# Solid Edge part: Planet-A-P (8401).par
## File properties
Title: Planet A/P
Author: DESYS
Template: Normal.par
Last saved by: s.pallini
Revision: 12
Application: Solid Edge
Tipo di contenuto documento: 0
Precisione: 0,990
Document Number: 8401
Revision: 0
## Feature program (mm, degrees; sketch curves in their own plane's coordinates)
lofted protrusion "unnamed LoftedProtrusion 1"
sketch for "unnamed Protrusion 1" plane through (0, 0, 447) normal (0, 0, 1) x-axis (1, 0, 0)
  line (-263.8082, -135) -> (-147.5635, -135)
  line (-263.8082, 135) -> (-263.8082, -135)
  line (-263.8082, 135) -> (-147.5635, 135)
  dimension (linear) = 263.8082
extrude "unnamed Protrusion 1" add to key point along -normal
sketch for "unnamed Cutout 1" plane through (0, 0, 0) normal (0, -1, 0) x-axis (1, 0, 0)
  line (-263.8082, 447) -> (211.175, 360)
extrude "unnamed Cutout 1" cut through
sketch for "ExtrudedCutout_2" plane through (0, 0, 430) normal (0, 0, 1) x-axis (1, 0, 0)
  circle centre (7.2353, 0) radius 173.2534
extrude "ExtrudedCutout_2" cut finite 110 along -normal
lofted cutout "unnamed LoftedCutout 1"
sketch for "ExtrudedCutout_3" plane through (0, 0, 0) normal (0, -1, 0) x-axis (1, 0, 0)
  line (-191.006, 180) -> (-191.006, -23.5209)
  line (-263.8082, 180) -> (-191.006, 180)
  line (-263.8082, 397) -> (-263.8082, 180)
  line (-263.8082, 397) -> (-173.278, 397)
  arc centre (-38.4455, 309.6496) radius 160.6546 from (-173.278, 397) to (-95.4684, 159.4555) ccw
  line (-95.4684, 159.4555) -> (-95.4684, 0)
extrude "ExtrudedCutout_3" cut finite 210 symmetric
sketch for "unnamed Cutout 2" plane through (0, 0, 0) normal (0, 0, 1) x-axis (1, 0, 0)
  line (-95.4684, -105) -> (8.5066, -95.764)
  arc centre (-2.9504, 0) radius 96.4469 from (8.5066, 95.764) to (8.5066, -95.764) cw
  line (-95.4684, 105) -> (8.5066, 95.764)
  line (-95.4684, 105) -> (-95.4684, -105)
extrude "unnamed Cutout 2" cut to key point along +normal
sketch for "ExtrudedProtrusion_2" plane through (0, 0, 190) normal (0, 0, 1) x-axis (1, 0, 0)
  line (-90, -70) -> (60, -70)
  line (60, -70) -> (60, 70)
  line (60, 70) -> (-90, 70)
  line (-90, 70) -> (-90, -70)
  dimension (linear) = 90
  dimension (linear) = 60
extrude "ExtrudedProtrusion_2" add finite 180 along -normal  Treatment1_DraftAngle = 5 deg
fillet "Rotondo_1" radius 40
fillet "Rotondo_2" radius 30
sketch for "unnamed Cutout 3" plane through (-263.8082, 0, 205) normal (-1, 0, 0) x-axis (0, -1, 0)
  line (-90, -25) -> (90, -25)
extrude "unnamed Cutout 3" cut through along -normal
sketch for "unnamed Protrusion 2" plane through (-263.8082, 0, 205) normal (-1, 0, 0) x-axis (0, -1, 0)
  circle centre (0, -20) radius 50
extrude "unnamed Protrusion 2" add through along -normal
sketch for "ExtrudedCutout_6" plane through (0, 0, 0) normal (0, -1, 0) x-axis (1, 0, 0)
  line (50, 190) -> (33.6666, 61.5312)
  arc centre (3.9062, 65.3149) radius 30 from (3.9062, 35.3149) to (33.6666, 61.5312) ccw
  line (-34.4205, 35.3149) -> (3.9062, 35.3149)
  arc centre (-34.4205, 65.3149) radius 30 from (-63.3356, 57.3198) to (-34.4205, 35.3149) ccw
  line (-63.3356, 57.3198) -> (-84.6468, 160.6314)
  line (-84.6468, 160.6314) -> (-147.9995, 220.4026)
  line (-147.9995, 220.4026) -> (-125.2315, 220.4026)
  line (-125.2315, 220.4026) -> (-67.5978, 188.5269)
  line (-46.1658, 66.9955) -> (-67.5978, 188.5269)
  arc centre (-38.2874, 68.3848) radius 8 from (-46.1658, 66.9955) to (-38.2874, 60.3848) ccw
  line (-33.9784, 60.3848) -> (-38.2874, 60.3848)
  arc centre (-33.9784, 64.3848) radius 4 from (-33.9784, 60.3848) to (-30.0285, 65.016) ccw
  line (-50, 190) -> (-30.0285, 65.016)
extrude "ExtrudedCutout_6" cut finite 100 symmetric
sketch for "unnamed Cutout 4" plane through (-263.8082, 0, 180) normal (-1, 0, 0) x-axis (0, -1, 0)
  circle centre (0, 5) radius 40
extrude "unnamed Cutout 4" cut to key point along -normal
sketch for "unnamed Cutout 5" plane through (-125.2315, 0, 169.4609) normal (-1, 0, 0) x-axis (0, -1, 0)
  arc centre (0, 15.5391) radius 40 from (37.4991, 29.4609) to (-37.4991, 29.4609) cw
  line (-37.4991, 29.4609) -> (37.4991, 29.4609)
extrude "unnamed Cutout 5" cut through along -normal
fillet "Rotondo_3" radius 10
fillet "Rotondo_4" radius 10
fillet "Rotondo_5" radius 30
fillet "Rotondo_6" radius 5
fillet "Rotondo_7" radius 15
fillet "Rotondo_8" radius 40
fillet "Rotondo_9" radius 10
fillet "Rotondo_10" radius 20
fillet "Rotondo_12" radius 5
sketch for "unnamed Protrusion 3" plane through (-263.8082, 0, 204.4547) normal (-1, 0, 0) x-axis (0, -1, 0)
  circle centre (0, 172.5453) radius 45
extrude "unnamed Protrusion 3" add through along -normal
sketch for "ExtrudedCutout_9" plane through (-263.8082, 0, 204.4547) normal (-1, 0, 0) x-axis (0, -1, 0)
  circle centre (0, 172.5453) radius 27.5
extrude "ExtrudedCutout_9" cut finite 80 along -normal
fillet "unnamed Round 1"
sketch for "Foro_1" plane through (-20.561, 0.5154, 402.4458) normal (0.180167, 0, 0.983636) x-axis (0, -1, 0)
  hole centre (90.5154, -175.296) bore radius 10
hole "Foro_1" diameter 20 through
sketch for "unnamed Hole 1" plane through (-20.561, 0.5154, 402.4458) normal (0.180167, 0, 0.983636) x-axis (0, -1, 0)
  hole centre (-89.4846, -175.296) bore radius 10
hole "unnamed Hole 1" through
pattern "unnamed Pattern 1" of "Foro_1", "unnamed Hole 1"
sketch for "RevolvedCutout_1" plane through (0, 0, 0) normal (0, -1, 0) x-axis (1, 0, 0)
revolve "RevolvedCutout_1" cut finite 260 deg
sketch for "ExtrudedProtrusion_5" #1 plane through (-120, 0, 0) normal (1, 0, 0) x-axis (0, 1, 0)
sketch for "ExtrudedProtrusion_5" #2 plane through (-120, 0, 0) normal (1, 0, 0) x-axis (0, 1, 0)
extrude "ExtrudedProtrusion_5" add to key point along +normal  Profile_Plane1_Distance = 120 mm
fillet "Rotondo_14" radius 5
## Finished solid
Body 1: solid body, 186 faces, 452 edges, 266 vertices.
  Faces by surface: cylinder 68, plane 48, blend 36, torus 25, sphere 8, spline 1
  Edges by curve: circle 170, line 158, intersection 91, ellipse 33
Bounding box of the edges (mm; curved faces can reach further): 485.297 x 429.897 x 445.380, from (-263.8082, -214.9482, -0.3778) to (221.4884, 214.9494, 445.002).
Cylindrical faces by radius (mm): R4 x1, R5 x28, R8 x1, R10 x14, R20 x2, R27.5 x1, R30 x8, R40 x7, R45 x1, R50 x1, R90 x1, R96.4469 x1, R160.6546 x1, R173.2534 x1
Toroidal faces (ring radius, tube radius in mm): R-323.8082 r550 x1, R5 r5 x4, R9 r5 x2, R10 r5 x6, R13 r5 x2, R40 r5 x1, R45 r5 x1, R60 r20 x2, R76.4469 r20 x1, R78.3106 r114.4885 x1, R95 r5 x2, R180.6546 r20 x2
Spherical faces by radius (mm): R5 x4, R10 x4
Planar faces by outward normal: +x 3, +y 4, +z 3, -x 4, -y 4, -z 12, oblique 18
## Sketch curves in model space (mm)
arc centre (0, 9.2575, 385.8062) radius 200 from (0, 50, 190) through (0, 141.1846, 235.489) to (0, 198.1213, 320)
arc centre (0, -9.2575, 385.8062) radius 200 from (0, -198.1213, 320) through (0, -141.1846, 235.489) to (0, -50, 190)
arc centre (-1.549, 0, 384.0425) radius 200 from (-191.0181, 0, 320) through (-137.1089, 0, 236.9932) to (-50, 0, 190)
arc centre (-4.692, 0, 413.4027) radius 230 from (205.4887, 0, 320) through (142.8356, 0, 236.9499) to (50, 0, 190)
arc centre (20, -20, 190) radius 30 from (20, -50, 190) through (41.8212, -40.5872, 190) to (50, -20, 190)
line (50, -20, 190) -> (50, 20, 190)
arc centre (20, 20, 190) radius 30 from (20, 50, 190) through (41.8212, 40.5872, 190) to (50, 20, 190)
line (20, 50, 190) -> (-45, 50, 190)
arc centre (-45, 45, 190) radius 5 from (-50, 45, 190) through (-48.4312, 48.6369, 190) to (-45, 50, 190)
line (-50, 45, 190) -> (-50, -45, 190)
arc centre (-45, -45, 190) radius 5 from (-50, -45, 190) through (-48.4312, -48.6369, 190) to (-45, -50, 190)
line (-45, -50, 190) -> (20, -50, 190)
circle centre (7.2353, 0, 320) radius 198.2534
arc centre (-323.8082, 0, 279.2951) radius 550 from (200, 0, 447) through (222.7829, 0, 218.1552) to (150, 0, 0)
circle centre (0, 0, 447) radius 200
circle centre (0, 0, 0) radius 150
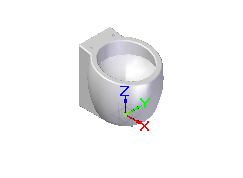
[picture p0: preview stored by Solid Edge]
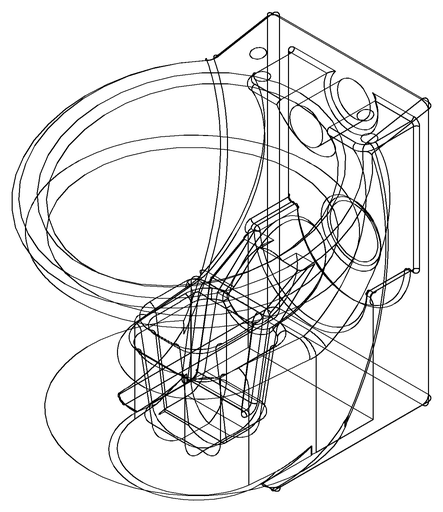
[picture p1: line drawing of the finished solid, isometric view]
